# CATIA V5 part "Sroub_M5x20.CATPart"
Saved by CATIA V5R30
Part number: Sroub_M5x20
Nomenclature: E1200/5x20
Description: MEUSBURGER
Publications: "DrillHole", "TapHole", "Base"
Bounding box of the stored display mesh (mm): x -4.249 to 4.249, y -4.245 to 4.245, z -5 to 20
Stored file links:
  E:\Bakalarka\Model\Forma_v7\Sroub_M5x20.CATPart
  E:\dev\MoldDesign\intel_a\startup\components\MoldCatalog\CapScrew\Meusburger\CapScrew_E1200\TableE1200.txt
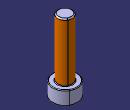
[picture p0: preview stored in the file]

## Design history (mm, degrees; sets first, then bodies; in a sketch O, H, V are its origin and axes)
Parameters
  Ref = "E1200/5x20" {design table}
  L = 20 mm {design table}
  D = 5 mm {design table}
  D1 = 5 mm {design table}
  D3 = 8.5 mm {design table}
  L1 = 20 mm {design table}
  L2 = 20 mm {design table}
  L3 = 5 mm {design table}
  SW = 4 mm {design table}
  dkren = 4.02 mm {design table}
  L4 = 2.5 mm {design table}
  R = 0.2 mm {design table}
  R1 = 0.5 mm {design table}
  F = 0.4 mm {design table}
  kdkern = 4.13 mm {design table}
  kd1 = 5.5 mm {design table}
  kl1 = 15 mm {design table}
  kd3 = 9.5 mm {design table}
  kl3 = 6 mm {design table}
  kl = 30 mm {design table}
  c = 4 mm {design table}
  ThreadString = "M5" {design table}
  Mat = "" {design table}
  HeatTreat = "" {design table}
  SupplierRef = "Meusburger 2017"
  BmpRef = "F_MldCapScrewLD"
  DrillHole_Length = 225 mm
  HeadThick = 5 mm {= L3}
  HeadDiam = 8.5 mm {= D3}
  ScrewThread = 20 mm {= Thread1.Depth}
  ScrewPitch = 0.8 mm {= Thread1.Pitch}
Set1 "BaseBody"
  Point1 "Base": (0, 0, 0)
  Plane1: type Offset, RefPlane xy-plane, Offset 225 {= DrillHole_Length}, reversed
Body1 "PartBody" (main body)
  Sketch1 on yz-plane, origin (0, 0, 0), H (0, 0, -1), V (0, 1, 0)
    point P1 (5, 0)
    line L1 (5, 0) -> (5, -4.25)
    line L2 (5, -4.25) -> (0, -4.25)
    line L3 (0, -4.25) -> (0, -2.5)
    point P5 (0, -2.5)
    line L4 (0, -2.5) -> (-20, -2.5)
    line L5 (-20, -2.5) -> (-20, 0)
    point P7 (-20, 0)
    axis line L6 (-20, 0) -> (5, 0)
    point P8 (5, 0)
    construction line L7 (0, -2.5) -> (0, -2.5)
    line L8 (0, 0) -> (-20, 0)
    point P9 (-20, -2.5)
    point P10 (-20, -2.5)
    line L9 (0, 0) -> (5, 0)
    length L1 = 4.25 {= D3 /2}
    distance L1 L3 = 5 {= L3}
    distance L4 L6 = 2.5 {= D /2}
    distance L3 L5 = 20 {= L}
    distance L5 P5 = 20 {= L1}
    coincidence: P1 L6, L6 H, P8 L1, P9 P10, P7 L5, L3 V
    vertical: L1 V, L3 V, L5 V
    horizontal: L2 H, L4 H, L7 H, L8 H, L9 H
  Shaft1: profile Sketch1, axis Sketch1.L6, angle 360
  Sketch2 on face of Shaft1 from Sketch1.L1, origin (0, 0, -5), H (1, 0, 0), V (0, -1, 0)
    point P1 (-1.1547, -2)
    point P2 (1.1547, -2)
    point P3 (2.3094, 0)
    point P4 (1.1547, 2)
    point P5 (-1.1547, 2)
    point P6 (-2.3094, 0)
    point P7 (0, -2)
    line L1 (-1.1547, -2) -> (1.1547, -2)
    line L2 (1.1547, -2) -> (2.3094, 0)
    line L3 (2.3094, 0) -> (1.1547, 2)
    line L4 (1.1547, 2) -> (-1.1547, 2)
    line L5 (-1.1547, 2) -> (-2.3094, 0)
    line L6 (-2.3094, 0) -> (-1.1547, -2)
    construction line L7 (0, 0) -> (0, -2)
    construction circle A1 centre (0, 0) radius 2.3094
    construction arc A2 centre (-1.1547, 2) radius 2.3094 from (1.1547, 2) to (-2.3094, 0) cw
    construction arc A3 centre (1.1547, -2) radius 2.3094 from (2.3094, 0) to (-1.1547, -2) ccw
    point P8 (-1.1547, 2)
    point P9 (1.1547, -2)
    distance L1 L4 = 4 {= SW}
    coincidence: A1 P1, A1 P2, A1 P3, A1 P4, A1 P5, A1 P6, A2 P4, A2 P6, A2 O, P8 P5, A3 P3, A3 P1, A3 O, P9 P2, P3 H
    midpoint: P7 L1
  Pocket1: profile Sketch2, direction (0, 0, 1), length 2.5 {= L4}
  Thread1: "M5", diameter 5, depth 20 {= L2}, pitch 0.8, on face of Shaft1 from Sketch1.L4, from face of Shaft1 from Sketch1.L5
  Fillet1: radius 0.5 {= R1}, on edge [face of Shaft1 from Sketch1.L2 | face of Shaft1 from Sketch1.L1]
  Fillet2: radius 0.2 {= R}, on edge [face of Shaft1 from Sketch1.L3 | face of Shaft1 from Sketch1.L2]
  Fillet3: radius 0.2 {= R}, on edge [face of Shaft1 from Sketch1.L4 | face of Shaft1 from Sketch1.L3]
  Chamfer1: length 0.4 {= F}, angle 45, on edge [face of Shaft1 from Sketch1.L5 | face of Shaft1 from Sketch1.L4]
Body2 "DrillHole"
  Sketch3 on Plane1, origin (22.3066, -22.3066, -225), H (1, 0, 0), V (0, 1, 0)
    point P1 (-22.3066, 22.3066)
    reference projected circle E1 centre (-22.3066, 22.3066) radius 4.25 from edge [face of Shaft1 from Sketch1.L3 | face of Shaft1 from Sketch1.L2]
    concentricity: E1 P1
  Hole1: placed by Sketch3, at (0, 0, -225) direction (0, 0, 1), diameter 5.5 {= kd1}, depth 245 {= DrillHole_Length +L1}, counterbore diameter 9.5 {= kd3}, counterbore depth 225 {= DrillHole_Length}
Body3 "TapHole"
  Sketch4 on Plane1, origin (0, 0, -225), H (1, 0, 0), V (0, 1, 0)
    point P1 (0, 0)
    reference projected point E1 (0, 0) from Point1
    coincidence: E1 P1
  Hole2: placed by Sketch4, at (0, 0, -225) direction (0, 0, 1), diameter 4.134, depth 255 {= DrillHole_Length +kl}, V-bottom angle 120, threaded "M5", thread diameter 5, thread depth 255 {= DrillHole_Length +kl}, pitch 0.8
Relations
  design table "TableE1200", configuration 35, drives Ref, L, D, D1, D3, L1, L2, L3, SW, dkren, L4, R, R1, F, kdkern, kd1, kl1, kd3, kl3, kl, c, ThreadString, Mat, HeatTreat
  Thread1.ThreadDescription = ThreadString
  Hole2.ThreadDescription = ThreadString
